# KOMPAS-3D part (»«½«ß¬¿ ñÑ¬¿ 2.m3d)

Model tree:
1. Эскиз:1
2. Операция выдавливания:1
     Толщина стенки 1 = 2.3; Толщина стенки 2 = 2.3; Расстояние 1 = 0.6; Расстояние 2 = 0.6
3. Эскиз:2
4. Операция выдавливания:2
     Толщина стенки 1 = 2.3; Толщина стенки 2 = 2.3; Расстояние 1 = 0.6; Расстояние 2 = 0.6
5. Эскиз:3
6. Вырезать элемент выдавливания:1
     Толщина стенки 1 = 3; Толщина стенки 2 = 3; Расстояние 1 = 10
7. Эскиз:4
8. Вырезать элемент выдавливания:2
     Толщина стенки 1 = 3; Толщина стенки 2 = 3; Расстояние 1 = 10
9. Вырезать элемент выдавливания:3
     Расстояние 1 = 10
